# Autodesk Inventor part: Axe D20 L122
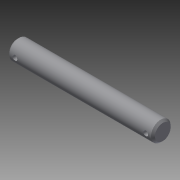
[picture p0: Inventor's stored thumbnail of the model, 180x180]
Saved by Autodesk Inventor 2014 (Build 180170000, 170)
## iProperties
Created: 2015-09
Part Number: Axe D20 L122
Material: Générique
Document SubType Name: Modeling
Designer: OL
Density: 1 g/cm^3
Appearance: Par défaut
Author: OL
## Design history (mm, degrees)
sketch "Esquisse1"
  geometry: C1 r 10 at (0, 0); 1 further point
  constraints: 1 centre point, 1 coincident
  dimensions: "d0" = 20 diameter of C1
extrude "Extrusion1" new body sketch "Esquisse1" distance "d2" = 148; taper "d3" = 0 deg
chamfer "Chanfrein1" distance "d4" = 2; stored, may be unused: second distance "d5" = 2, angle "d6" = 45 deg
sketch "Esquisse2"
  geometry: C1 r 2.5 at (-140.5, 0); C2 r 2.5 at (-7.5, 0); 1 further point
  constraints: 2 centre point
  dimensions: "d7" = 5 diameter of C1; "d9" = 5 diameter of C2; "d10" = 7.5 distance of point (0, 0) C2.centre; "d11" = 140.5 distance of point (0, 0) C1.centre
extrude "Extrusion2" cut sketch "Esquisse2" stored distance "d13" = 100; taper "d14" = 0 deg
node "Solide1"
